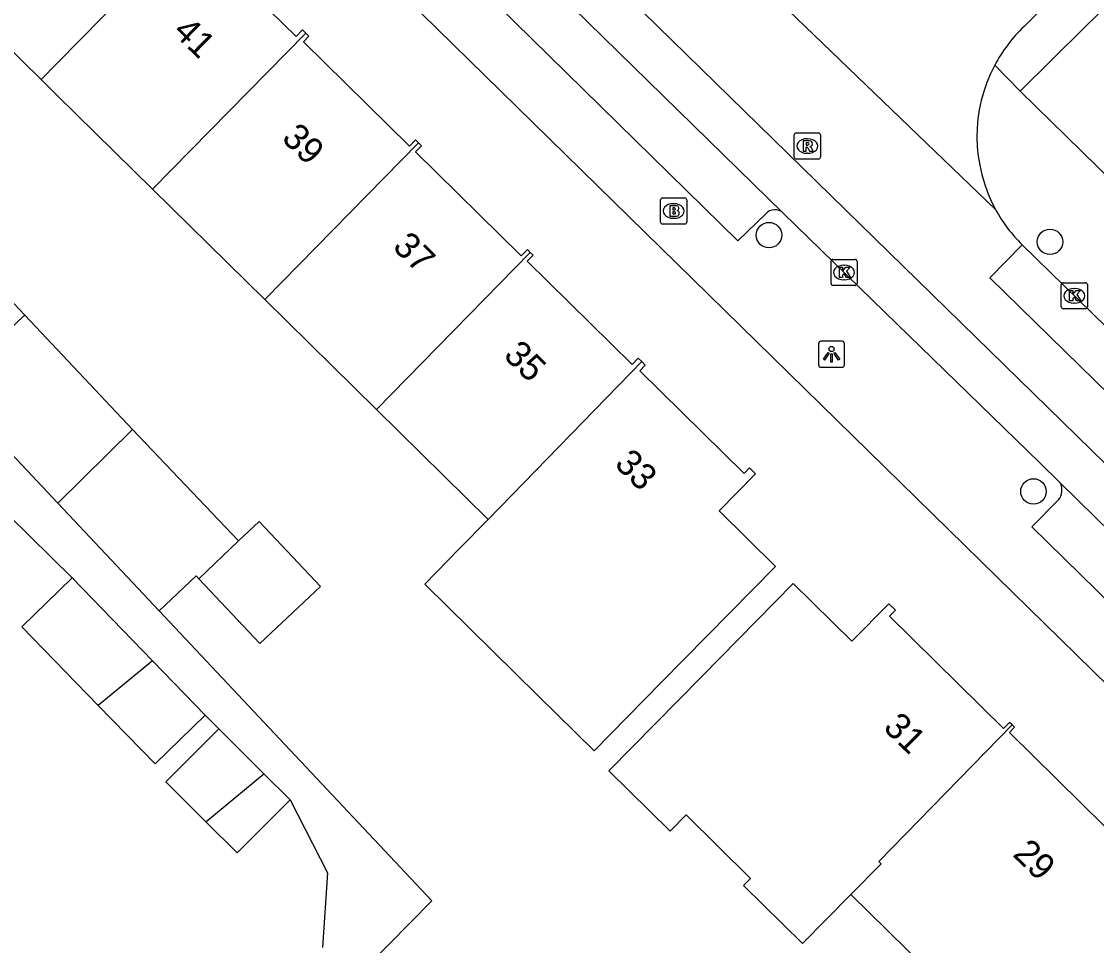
# Model space of a CAD drawing. Extents: x 159222 to 160346, y 381249 to 382166.
# Drawn here: x 159998.63 to 160039.91, y 381712.59 to 381748.05 of the extents above; entities that cross this region are included whole.
import ezdxf

# ---------------------------------------------------------------- set-up
doc = ezdxf.new("R2010")
doc.units = 0
for name, color, linetype in [('IMGEO_Boom', 7, 'Continuous'), ('IMGEO_Brandkraan', 7, 'Continuous'), ('IMGEO_Kolk', 7, 'Continuous'), ('IMGEO_Lichtpunt', 7, 'Continuous'), ('IMGEO_Pand', 7, 'Continuous'), ('IMGEO_Pand_nummerreeks', 7, 'Continuous'), ('IMGEO_Rijbaan_lokaal_gesloten', 7, 'Continuous'), ('IMGEO_Rijbaan_lokaal_open', 7, 'Continuous'), ('IMGEO_Rioolput', 7, 'Continuous'), ('IMGEO_Voetpad_open', 7, 'Continuous')]:
    doc.layers.add(name, color=color, linetype=linetype)

msp = doc.modelspace()

# ---------------------------------------------------------------- linework, layer by layer
at = {"layer": 'IMGEO_Boom'}
for centre in [(160027.331, 381739.855), (160038.12, 381739.598), (160037.486, 381730.016)]:
    msp.add_circle(centre, 0.489, dxfattribs=at)
at = {"layer": 'IMGEO_Brandkraan'}
for p, q in [((160023.171, 381740.355), (160023.171, 381741.207)), ((160023.246, 381741.281), (160024.098, 381741.281)), ((160023.659, 381741.061), (160023.684, 381741.061)), ((160024.172, 381741.207), (160024.172, 381740.355)), ((160024.098, 381740.281), (160023.246, 381740.281)), ((160023.682, 381740.501), (160023.657, 381740.501))]:
    msp.add_line(p, q, dxfattribs=at)
for points in [[(160023.171, 381740.355), (160023.171, 381741.207)], [(160023.246, 381741.281), (160024.098, 381741.281)], [(160023.519, 381740.981), (160023.519, 381740.581), (160023.732, 381740.581)], [(160023.75, 381740.981), (160023.519, 381740.981)], [(160024.172, 381741.207), (160024.172, 381740.355)], [(160023.698, 381740.9), (160023.644, 381740.9), (160023.644, 381740.824)], [(160023.644, 381740.824), (160023.697, 381740.824)], [(160023.706, 381740.748), (160023.644, 381740.748), (160023.644, 381740.667)], [(160023.644, 381740.667), (160023.706, 381740.667)], [(160024.098, 381740.281), (160023.246, 381740.281)]]:
    msp.add_lwpolyline(points, dxfattribs=at)
for centre, radius, start, end in [((160023.248, 381741.205), 0.0765, 91.552, 178.448), ((160023.248, 381741.205), 0.0765, 91.552, 178.448), ((160023.754, 381740.836), 0.145, 59.4692, 91.5367), ((160023.779, 381740.883), 0.0922, 285.5137, 58.1501), ((160024.096, 381741.205), 0.0765, 1.552, 88.448), ((160024.096, 381741.205), 0.0765, 1.552, 88.448), ((160023.699, 381740.862), 0.0379, 267.8285, 90.9355), ((160023.707, 381740.707), 0.0404, 269.8759, 90.5077), ((160023.738, 381740.832), 0.251, 268.6676, 293.5347), ((160023.784, 381740.691), 0.105, 301.3115, 78.989), ((160023.248, 381740.357), 0.0765, 181.552, 268.448), ((160023.248, 381740.357), 0.0765, 181.552, 268.448), ((160024.096, 381740.357), 0.0765, 271.552, 358.448), ((160024.096, 381740.357), 0.0765, 271.552, 358.448)]:
    msp.add_arc(centre, radius, start, end, dxfattribs=at)
for centre, major_axis, ratio, start_param, end_param in [((160023.658, 381740.781), (-0.387, 0.002), 0.722429, 4.712389, 7.853982), ((160023.683, 381740.781), (-0.39, 0.002), 0.717154, 1.570796, 4.712389)]:
    msp.add_ellipse(centre, major_axis=major_axis, ratio=ratio, start_param=start_param, end_param=end_param, dxfattribs=at)
at = {"layer": 'IMGEO_Kolk'}
for p, q in [((160029.788, 381738.924), (160030.64, 381738.924)), ((160029.713, 381737.998), (160029.713, 381738.85)), ((160030.201, 381738.704), (160030.226, 381738.704)), ((160030.714, 381738.85), (160030.714, 381737.998)), ((160030.224, 381738.144), (160030.199, 381738.144)), ((160030.64, 381737.924), (160029.788, 381737.924)), ((160038.554, 381737.102), (160038.554, 381737.954)), ((160038.629, 381738.028), (160039.481, 381738.028)), ((160039.042, 381737.808), (160039.067, 381737.808)), ((160039.555, 381737.954), (160039.555, 381737.102)), ((160039.065, 381737.248), (160039.04, 381737.248)), ((160039.481, 381737.028), (160038.629, 381737.028))]:
    msp.add_line(p, q, dxfattribs=at)
for points in [[(160029.788, 381738.924), (160030.64, 381738.924)], [(160029.713, 381737.998), (160029.713, 381738.85)], [(160030.034, 381738.624), (160030.157, 381738.624), (160030.157, 381738.473), (160030.287, 381738.624), (160030.451, 381738.624), (160030.305, 381738.473), (160030.458, 381738.224), (160030.306, 381738.224), (160030.221, 381738.388), (160030.157, 381738.321), (160030.157, 381738.224), (160030.034, 381738.224), (160030.034, 381738.624)], [(160030.714, 381738.85), (160030.714, 381737.998)], [(160030.64, 381737.924), (160029.788, 381737.924)], [(160038.554, 381737.102), (160038.554, 381737.954)], [(160038.629, 381738.028), (160039.481, 381738.028)], [(160038.875, 381737.728), (160038.998, 381737.728), (160038.998, 381737.577), (160039.128, 381737.728), (160039.292, 381737.728), (160039.146, 381737.577), (160039.299, 381737.328), (160039.147, 381737.328), (160039.062, 381737.492), (160038.998, 381737.425), (160038.998, 381737.328), (160038.875, 381737.328), (160038.875, 381737.728)], [(160039.555, 381737.954), (160039.555, 381737.102)], [(160039.481, 381737.028), (160038.629, 381737.028)]]:
    msp.add_lwpolyline(points, dxfattribs=at)
for centre, start, end in [((160029.79, 381738.848), 91.552, 178.448), ((160029.79, 381738.848), 91.552, 178.448), ((160030.638, 381738.848), 1.552, 88.448), ((160030.638, 381738.848), 1.552, 88.448), ((160029.79, 381738), 181.552, 268.448), ((160029.79, 381738), 181.552, 268.448), ((160030.638, 381738), 271.552, 358.448), ((160030.638, 381738), 271.552, 358.448), ((160038.631, 381737.952), 91.552, 178.448), ((160038.631, 381737.952), 91.552, 178.448), ((160039.479, 381737.952), 1.552, 88.448), ((160039.479, 381737.952), 1.552, 88.448), ((160038.631, 381737.104), 181.552, 268.448), ((160038.631, 381737.104), 181.552, 268.448), ((160039.479, 381737.104), 271.552, 358.448), ((160039.479, 381737.104), 271.552, 358.448)]:
    msp.add_arc(centre, 0.0765, start, end, dxfattribs=at)
for centre, major_axis, ratio, start_param, end_param in [((160030.2, 381738.424), (-0.387, 0.002), 0.722429, 4.712389, 7.853982), ((160030.225, 381738.424), (-0.39, 0.002), 0.717154, 1.570796, 4.712389), ((160039.041, 381737.528), (-0.387, 0.002), 0.722429, 4.712389, 7.853982), ((160039.066, 381737.528), (-0.39, 0.002), 0.717154, 1.570796, 4.712389)]:
    msp.add_ellipse(centre, major_axis=major_axis, ratio=ratio, start_param=start_param, end_param=end_param, dxfattribs=at)
at = {"layer": 'IMGEO_Lichtpunt'}
for p, q in [((160029.234, 381735.687), (160029.234, 381734.88)), ((160029.234, 381735.687), (160029.234, 381734.88)), ((160030.136, 381735.782), (160029.328, 381735.782)), ((160030.136, 381735.782), (160029.328, 381735.782)), ((160030.23, 381734.88), (160030.23, 381735.687)), ((160030.23, 381734.88), (160030.23, 381735.687)), ((160029.328, 381734.786), (160030.136, 381734.786)), ((160029.328, 381734.786), (160030.136, 381734.786))]:
    msp.add_line(p, q, dxfattribs=at)
for points in [[(160029.608, 381735.351), (160029.647, 381735.323), (160029.459, 381735.061), (160029.421, 381735.088), (160029.608, 381735.351)], [(160029.71, 381735.303), (160029.757, 381735.303), (160029.757, 381734.981), (160029.71, 381734.981), (160029.71, 381735.303)], [(160029.82, 381735.323), (160029.858, 381735.35), (160030.045, 381735.088), (160030.006, 381735.06), (160029.82, 381735.323)]]:
    msp.add_lwpolyline(points, dxfattribs=at)
msp.add_circle((160029.733, 381735.485), 0.0994, dxfattribs=at)
for centre, start, end in [((160029.328, 381735.687), 90, 180), ((160029.328, 381735.687), 90, 180), ((160030.136, 381735.687), 0, 90), ((160030.136, 381735.687), 0, 90), ((160029.328, 381734.88), 180, 270), ((160029.328, 381734.88), 180, 270), ((160030.136, 381734.88), 270, 0), ((160030.136, 381734.88), 270, 360)]:
    msp.add_arc(centre, 0.0946, start, end, dxfattribs=at)
at = {"layer": 'IMGEO_Pand'}
for points in [[(159999.385, 381745.823), (160000, 381746.45), (160003.48, 381750), (160005.255, 381751.81)], [(160005.255, 381751.81), (160005.382, 381751.685), (160005.142, 381751.442), (160006.609, 381750), (160009.173, 381747.479), (160009.421, 381747.731), (160009.543, 381747.611)], [(159999.385, 381745.823), (159995.07, 381750.065)], [(160009.543, 381747.611), (160003.664, 381741.615)], [(160009.543, 381747.611), (160009.664, 381747.492), (160009.453, 381747.277), (160013.522, 381743.272), (160013.761, 381743.515), (160013.878, 381743.4)], [(160003.664, 381741.615), (160000, 381745.218), (159999.385, 381745.823)], [(160013.878, 381743.4), (160007.974, 381737.378)], [(160013.878, 381743.4), (160013.993, 381743.286), (160013.765, 381743.055), (160017.819, 381739.064), (160018.053, 381739.301), (160018.164, 381739.192)], [(160007.974, 381737.378), (160003.664, 381741.615)], [(159991.906, 381738.175), (159994.838, 381740.941), (159998.756, 381736.788)], [(160012.256, 381733.167), (160018.164, 381739.192)], [(160018.164, 381739.192), (160018.274, 381739.084), (160018.051, 381738.858), (160022.077, 381734.894), (160022.311, 381735.132), (160022.446, 381734.999)], [(160012.256, 381733.167), (160007.974, 381737.378)], [(159995.84, 381734.005), (159998.722, 381736.754), (159998.756, 381736.788)], [(159998.756, 381736.788), (160002.898, 381732.397)], [(160022.446, 381734.999), (160022.581, 381734.866), (160022.368, 381734.65), (160026.374, 381730.707), (160026.583, 381730.919), (160026.809, 381730.697), (160025.412, 381729.277), (160027.582, 381727.141), (160024.075, 381723.578), (160023.197, 381722.686), (160020.613, 381720.061), (160018.459, 381722.182), (160014.115, 381726.459), (160015.42, 381727.798), (160016.549, 381728.946)], [(160022.446, 381734.999), (160016.549, 381728.946)], [(160000.021, 381729.573), (159995.84, 381734.005)], [(160016.549, 381728.946), (160012.256, 381733.167)], [(160002.898, 381732.397), (160000.021, 381729.573)], [(160002.898, 381732.397), (160006.962, 381728.116)], [(160003.92, 381725.439), (160000.021, 381729.573)], [(160006.962, 381728.116), (160007.75, 381728.868), (160010.107, 381726.37), (160007.785, 381724.18), (160005.441, 381726.664)], [(160006.962, 381728.116), (160005.441, 381726.664)], [(160001.581, 381721.798), (159998.64, 381724.824), (160000.571, 381726.7)], [(160000.571, 381726.7), (160003.661, 381723.52)], [(160005.441, 381726.664), (160005.336, 381726.775), (160003.92, 381725.439)], [(160036.665, 381721.058), (160036.569, 381721.152), (160036.336, 381720.915), (160031.955, 381725.226), (160032.186, 381725.461), (160031.933, 381725.709), (160030.511, 381724.265), (160028.262, 381726.479), (160024.755, 381722.916), (160021.185, 381719.288), (160023.533, 381716.976), (160024.151, 381717.604), (160026.627, 381715.167), (160026.355, 381714.891), (160028.617, 381712.665), (160030.475, 381714.552)], [(160003.661, 381723.52), (160001.581, 381721.798)], [(160003.661, 381723.52), (160005.688, 381721.434)], [(160005.688, 381721.434), (160003.758, 381719.558), (160001.581, 381721.798)], [(160005.709, 381717.337), (160004.173, 381718.873), (160006.211, 381720.911)], [(160006.211, 381720.911), (160007.938, 381719.184)], [(160030.475, 381714.552), (160031.634, 381715.729), (160031.544, 381715.817), (160036.665, 381721.058)], [(160036.665, 381721.058), (160036.758, 381720.966), (160036.564, 381720.768), (160042.06, 381715.358), (160042.328, 381715.63), (160042.533, 381715.428), (160041.619, 381714.499), (160044.12, 381712.037), (160040.613, 381708.474), (160036.098, 381703.886), (160032.223, 381707.7), (160034.788, 381710.306), (160030.475, 381714.552)], [(160005.709, 381717.337), (160007.938, 381719.184)], [(160007.938, 381719.184), (160008.945, 381718.178)], [(160008.945, 381718.178), (160006.906, 381716.14), (160005.709, 381717.337)]]:
    msp.add_lwpolyline(points, dxfattribs=at)
at = {"layer": 'IMGEO_Rijbaan_lokaal_gesloten'}
for points in [[(160003.627, 381766.866), (160086.891, 381685.528)], [(160004.223, 381763.833), (160027.881, 381740.702)], [(160026.065, 381750.422), (160036.033, 381740.837)], [(160038.514, 381730.346), (160037.732, 381731.113), (160031.781, 381736.894), (160027.881, 381740.702)], [(160060.004, 381716.996), (160058.783, 381715.757), (160035.813, 381738.222), (160037.054, 381739.484)], [(160037.054, 381739.484), (160040.288, 381736.324), (160043.755, 381732.931), (160045.512, 381731.24)], [(160038.514, 381730.346), (160047.789, 381721.257)]]:
    msp.add_lwpolyline(points, dxfattribs=at)
msp.add_arc((160041.135, 381743.625), 5.814, 208.6572, 225.4206, dxfattribs=at)
at = {"layer": 'IMGEO_Rijbaan_lokaal_open'}
msp.add_lwpolyline([(160037.126, 381747.862), (160038.897, 381749.648), (160046.763, 381757.445), (160051.647, 381762.294), (160051.848, 381762.494)], dxfattribs=at)
for centre, radius, start, end in [((160041.189, 381743.607), 5.883, 133.677, 151.9452), ((160041.147, 381743.639), 5.832, 152.0291, 208.7159)]:
    msp.add_arc(centre, radius, start, end, dxfattribs=at)
at = {"layer": 'IMGEO_Rioolput'}
for p, q in [((160028.302, 381742.849), (160028.302, 381743.701)), ((160028.377, 381743.775), (160029.229, 381743.775)), ((160028.79, 381743.555), (160028.815, 381743.555)), ((160029.303, 381743.701), (160029.303, 381742.849)), ((160028.813, 381742.995), (160028.788, 381742.995)), ((160029.229, 381742.775), (160028.377, 381742.775))]:
    msp.add_line(p, q, dxfattribs=at)
for points in [[(160028.302, 381742.849), (160028.302, 381743.701)], [(160028.377, 381743.775), (160029.229, 381743.775)], [(160028.891, 381743.473), (160028.639, 381743.475), (160028.639, 381743.075)], [(160029.303, 381743.701), (160029.303, 381742.849)], [(160028.639, 381743.075), (160028.763, 381743.075), (160028.763, 381743.237), (160028.774, 381743.237)], [(160028.817, 381743.394), (160028.763, 381743.394), (160028.763, 381743.313)], [(160028.763, 381743.313), (160028.815, 381743.313)], [(160028.821, 381743.208), (160028.892, 381743.075), (160029.032, 381743.075), (160028.967, 381743.201)], [(160029.229, 381742.775), (160028.377, 381742.775)]]:
    msp.add_lwpolyline(points, dxfattribs=at)
for centre, radius, start, end in [((160028.379, 381743.699), 0.0765, 91.552, 178.448), ((160028.379, 381743.699), 0.0765, 91.552, 178.448), ((160028.89, 381743.363), 0.109, 350.3612, 89.416), ((160029.227, 381743.699), 0.0765, 1.552, 88.448), ((160029.227, 381743.699), 0.0765, 1.552, 88.448), ((160028.773, 381743.184), 0.0533, 26.0293, 88.6989), ((160028.799, 381743.502), 0.19, 274.7715, 282.9687), ((160028.823, 381743.298), 0.0964, 77.0061, 93.1865), ((160028.837, 381743.355), 0.0378, 276.6634, 79.6772), ((160028.888, 381743.363), 0.112, 277.5842, 350.9817), ((160028.872, 381743.148), 0.108, 29.5134, 73.7905), ((160028.379, 381742.851), 0.0765, 181.552, 268.448), ((160028.379, 381742.851), 0.0765, 181.552, 268.448), ((160029.227, 381742.851), 0.0765, 271.552, 358.448), ((160029.227, 381742.851), 0.0765, 271.552, 358.448)]:
    msp.add_arc(centre, radius, start, end, dxfattribs=at)
for centre, major_axis, ratio, start_param, end_param in [((160028.789, 381743.275), (-0.387, 0.002), 0.722429, 4.712389, 7.853982), ((160028.814, 381743.275), (-0.39, 0.002), 0.717154, 1.570796, 4.712389)]:
    msp.add_ellipse(centre, major_axis=major_axis, ratio=ratio, start_param=start_param, end_param=end_param, dxfattribs=at)
at = {"layer": 'IMGEO_Voetpad_open'}
for points in [[(160036.974, 381745.385), (160039.427, 381747.809), (160041.655, 381750), (160050.55, 381758.857), (160051.097, 381758.308), (160051.958, 381757.444), (160054.938, 381760.405), (160082.209, 381787.431)], [(160066.135, 381697.331), (159998.033, 381763.997)], [(160027.205, 381740.671), (160026.141, 381739.632), (160014.278, 381751.26), (160015.101, 381752.076)], [(160035.997, 381746.374), (160036.974, 381745.385)], [(160066.656, 381716.348), (160036.974, 381745.385)], [(159997.321, 381729.885), (160000.571, 381726.7)], [(160047.157, 381721.216), (160046.644, 381720.706), (160046.099, 381720.164), (160037.427, 381728.654), (160038.442, 381729.69)], [(160003.92, 381725.439), (160014.385, 381714.309), (160011.888, 381711.769)], [(160005.688, 381721.434), (160006.211, 381720.911)], [(160008.945, 381718.178), (160010.383, 381715.374), (160010.186, 381712.514)]]:
    msp.add_lwpolyline(points, dxfattribs=at)
for centre, radius, start, end in [((160027.558, 381740.363), 0.468, 46.3258, 138.9254), ((160037.99, 381730.072), 0.591, 319.825, 27.648)]:
    msp.add_arc(centre, radius, start, end, dxfattribs=at)

# ---------------------------------------------------------------- texts
at = {"layer": 'IMGEO_Pand_nummerreeks'}
for s, rotation, p in [('41', 315.6198, (160004.402, 381747.619)), ('39', 315.6198, (160008.581, 381743.529)), ('37', 315.6198, (160012.841, 381739.361)), ('35', 315.6198, (160017.1, 381735.193)), ('33', 315.6187, (160021.36, 381731.025)), ('31', 315.6817, (160031.678, 381720.91)), ('29', 315.6798, (160036.652, 381716.055))]:
    msp.add_text(s, height=1, rotation=rotation, dxfattribs=at).set_placement(p)

doc.saveas('drawing.dxf')
